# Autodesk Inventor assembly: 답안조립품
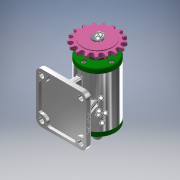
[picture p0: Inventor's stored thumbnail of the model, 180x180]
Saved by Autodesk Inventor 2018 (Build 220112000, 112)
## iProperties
Created: 2019-06
Part Number: 답안조립품
Document SubType Name: Assembly
Designer: Administrator
Author: Administrator
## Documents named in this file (11)
- C:\Users\Administrator\Desktop\490604V1042\답안조립품.iam
- C:\Users\Administrator\Desktop\490604V1042\본체.ipt
- C:\Users\Administrator\Desktop\490604V1042\베어링 6203.ipt
- C:\Users\Administrator\Desktop\490604V1042\스프로킷.ipt
- C:\Users\Administrator\Desktop\490604V1042\볼트 M4.ipt
- C:\Users\Administrator\Desktop\490604V1042\스프링와셔.ipt
- C:\Users\Administrator\Desktop\490604V1042\오일 실 17 30 5.ipt
- C:\Users\Administrator\Desktop\490604V1042\축.ipt
- C:\Users\Administrator\Desktop\490604V1042\커버.ipt
- C:\Users\Administrator\Desktop\490604V1042\키 4x4x12.ipt
- C:\Users\Administrator\Desktop\490604V1042\평와셔.ipt
